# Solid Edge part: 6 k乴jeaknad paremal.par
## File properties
Author: Henri
Template: Normal.par
Last saved by: Henri
Revision: 20
Application: Solid Edge
Accuracy: 0,990
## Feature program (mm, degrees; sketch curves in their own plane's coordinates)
sketch used by "unnamed Protrusion 1" plane through (0.1912, -510.5703, 43.2891) normal (0, -0.948683, 0.316228) x-axis (1, 0, 0)
  line (-72.6912, 35.6338) -> (17.3088, 35.6338)
  line (22.3088, 30.6338) -> (22.3088, 15.6338)
  line (-187.6912, 30.6338) -> (-187.6912, 15.6338)
  line (-72.6912, 10.6338) -> (17.3088, 10.6338)
  line (-87.6912, 30.6338) -> (-87.6912, 15.6338)
  line (-77.6912, 30.6338) -> (-77.6912, 15.6338)
  line (-182.6912, 10.6338) -> (-92.6912, 10.6338)
  line (-182.6912, 35.6338) -> (-92.6912, 35.6338)
  arc centre (-182.6912, 30.6338) radius 5 from (-187.6912, 30.6338) to (-182.6912, 35.6338) cw
  arc centre (-182.6912, 15.6338) radius 5 from (-187.6912, 15.6338) to (-182.6912, 10.6338) ccw
  arc centre (-92.6912, 15.6338) radius 5 from (-92.6912, 10.6338) to (-87.6912, 15.6338) ccw
  arc centre (-92.6912, 30.6338) radius 5 from (-87.6912, 30.6338) to (-92.6912, 35.6338) ccw
  arc centre (-72.6912, 30.6338) radius 5 from (-77.6912, 30.6338) to (-72.6912, 35.6338) cw
  arc centre (-72.6912, 15.6338) radius 5 from (-77.6912, 15.6338) to (-72.6912, 10.6338) ccw
  arc centre (17.3088, 15.6338) radius 5 from (17.3088, 10.6338) to (22.3088, 15.6338) ccw
  arc centre (17.3088, 30.6338) radius 5 from (22.3088, 30.6338) to (17.3088, 35.6338) ccw
extrude "unnamed Protrusion 1" add finite 5 along -normal
sketch for "ExtrudedProtrusion_14" #1 plane through (-137.5, -503.2547, 65.2358) normal (0, -0.948683, 0.316228) x-axis (1, 0, 0)
sketch for "ExtrudedProtrusion_14" #2 plane through (-137.5, -503.2547, 65.2358) normal (0, -0.948683, 0.316228) x-axis (1, 0, 0)
sketch for "ExtrudedProtrusion_14" #3 plane through (-137.5, -503.2547, 65.2358) normal (0, -0.948683, 0.316228) x-axis (1, 0, 0)
  line (-45, 11) -> (45, 11)
  arc centre (45, 7.5) radius 3.5 from (48.5, 7.5) to (45, 11) ccw
  line (48.5, 7.5) -> (48.5, -7.5)
  arc centre (45, -7.5) radius 3.5 from (45, -11) to (48.5, -7.5) ccw
  line (-45, -11) -> (45, -11)
  arc centre (-45, -7.5) radius 3.5 from (-48.5, -7.5) to (-45, -11) ccw
  line (-48.5, 7.5) -> (-48.5, -7.5)
  arc centre (-45, 7.5) radius 3.5 from (-48.5, 7.5) to (-45, 11) cw
sketch for "ExtrudedProtrusion_14" #4 plane through (-137.5, -503.2547, 65.2358) normal (0, -0.948683, 0.316228) x-axis (1, 0, 0)
  line (65, 14) -> (155, 14)
  arc centre (155, 7.5) radius 6.5 from (161.5, 7.5) to (155, 14) ccw
  line (161.5, 7.5) -> (161.5, -7.5)
  arc centre (155, -7.5) radius 6.5 from (155, -14) to (161.5, -7.5) ccw
  line (65, -14) -> (155, -14)
  arc centre (65, -7.5) radius 6.5 from (58.5, -7.5) to (65, -14) ccw
  line (58.5, 7.5) -> (58.5, -7.5)
  arc centre (65, 7.5) radius 6.5 from (58.5, 7.5) to (65, 14) cw
extrude "ExtrudedProtrusion_14" add finite 1.5 along +normal
fillet "Round_19" radius 0.5
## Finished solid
Body 1: solid body, 88 faces, 208 edges, 128 vertices, 2 separate solids.
  Faces by surface: cylinder 40, plane 32, torus 16
  Edges by curve: line 112, circle 96
Bounding box of the edges (mm; curved faces can reach further): 213.000 x 14.414 x 27.063, from (-189, -508.9725, 51.7961) to (24, -494.5585, 78.8592).
Cylindrical faces by radius (mm): R0.5 x16, R3.5 x8, R5 x8, R6.5 x8
Toroidal faces (ring radius, tube radius in mm): R4 r0.5 x8, R6 r0.5 x8
Planar faces by outward normal: +x 6, -x 6, oblique 20
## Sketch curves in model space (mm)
line (-182.5, -498.8276, 78.5173) -> (-92.5, -498.8276, 78.5173)
arc centre (-92.5, -500.883, 72.3509) radius 6.5 from (-86, -500.883, 72.3509) through (-88.0394, -499.3879, 76.8362) to (-92.5, -498.8276, 78.5173)
line (-86, -500.883, 72.3509) -> (-86, -505.6265, 58.1206)
arc centre (-92.5, -505.6265, 58.1206) radius 6.5 from (-92.5, -507.6819, 51.9542) through (-87.7721, -507.037, 53.889) to (-86, -505.6265, 58.1206)
line (-182.5, -507.6819, 51.9542) -> (-92.5, -507.6819, 51.9542)
arc centre (-182.5, -505.6265, 58.1206) radius 6.5 from (-189, -505.6265, 58.1206) through (-186.9606, -507.1216, 53.6353) to (-182.5, -507.6819, 51.9542)
line (-189, -500.883, 72.3509) -> (-189, -505.6265, 58.1206)
arc centre (-182.5, -500.883, 72.3509) radius 6.5 from (-189, -500.883, 72.3509) through (-186.9606, -499.3879, 76.8362) to (-182.5, -498.8276, 78.5173)
line (-182.5, -499.7762, 75.6713) -> (-92.5, -499.7762, 75.6713)
arc centre (-92.5, -500.883, 72.3509) radius 3.5 from (-89, -500.883, 72.3509) through (-90.0982, -500.078, 74.7661) to (-92.5, -499.7762, 75.6713)
line (-89, -500.883, 72.3509) -> (-89, -505.6265, 58.1206)
arc centre (-92.5, -505.6265, 58.1206) radius 3.5 from (-92.5, -506.7333, 54.8002) through (-89.9542, -506.386, 55.842) to (-89, -505.6265, 58.1206)
line (-182.5, -506.7333, 54.8002) -> (-92.5, -506.7333, 54.8002)
arc centre (-182.5, -505.6265, 58.1206) radius 3.5 from (-186, -505.6265, 58.1206) through (-184.9018, -506.4315, 55.7055) to (-182.5, -506.7333, 54.8002)
line (-186, -500.883, 72.3509) -> (-186, -505.6265, 58.1206)
arc centre (-182.5, -500.883, 72.3509) radius 3.5 from (-186, -500.883, 72.3509) through (-184.9018, -500.078, 74.7661) to (-182.5, -499.7762, 75.6713)
arc centre (17.5, -500.883, 72.3509) radius 6.5 from (24, -500.883, 72.3509) through (21.9606, -499.3879, 76.8362) to (17.5, -498.8276, 78.5173)
line (24, -500.883, 72.3509) -> (24, -505.6265, 58.1206)
arc centre (17.5, -505.6265, 58.1206) radius 6.5 from (17.5, -507.6819, 51.9542) through (22.2279, -507.037, 53.889) to (24, -505.6265, 58.1206)
line (-72.5, -507.6819, 51.9542) -> (17.5, -507.6819, 51.9542)
arc centre (-72.5, -505.6265, 58.1206) radius 6.5 from (-79, -505.6265, 58.1206) through (-76.9606, -507.1216, 53.6353) to (-72.5, -507.6819, 51.9542)
line (-79, -500.883, 72.3509) -> (-79, -505.6265, 58.1206)
arc centre (-72.5, -500.883, 72.3509) radius 6.5 from (-79, -500.883, 72.3509) through (-76.9606, -499.3879, 76.8362) to (-72.5, -498.8276, 78.5173)
line (-72.5, -498.8276, 78.5173) -> (17.5, -498.8276, 78.5173)
line (-72.5, -499.7762, 75.6713) -> (17.5, -499.7762, 75.6713)
arc centre (17.5, -500.883, 72.3509) radius 3.5 from (21, -500.883, 72.3509) through (19.9018, -500.078, 74.7661) to (17.5, -499.7762, 75.6713)
line (21, -500.883, 72.3509) -> (21, -505.6265, 58.1206)
arc centre (17.5, -505.6265, 58.1206) radius 3.5 from (17.5, -506.7333, 54.8002) through (20.0458, -506.386, 55.842) to (21, -505.6265, 58.1206)
line (-72.5, -506.7333, 54.8002) -> (17.5, -506.7333, 54.8002)
arc centre (-72.5, -505.6265, 58.1206) radius 3.5 from (-76, -505.6265, 58.1206) through (-74.9018, -506.4315, 55.7055) to (-72.5, -506.7333, 54.8002)
line (-76, -500.883, 72.3509) -> (-76, -505.6265, 58.1206)
arc centre (-72.5, -500.883, 72.3509) radius 3.5 from (-76, -500.883, 72.3509) through (-74.9018, -500.078, 74.7661) to (-72.5, -499.7762, 75.6713)
arc centre (17.5, -500.883, 72.3509) radius 5 from (22.5, -500.883, 72.3509) through (20.9312, -499.733, 75.8011) to (17.5, -499.3019, 77.0943)
line (22.5, -500.883, 72.3509) -> (22.5, -505.6265, 58.1206)
arc centre (17.5, -505.6265, 58.1206) radius 5 from (17.5, -507.2076, 53.3772) through (21.1369, -506.7115, 54.8655) to (22.5, -505.6265, 58.1206)
line (-72.5, -507.2076, 53.3772) -> (17.5, -507.2076, 53.3772)
arc centre (-72.5, -505.6265, 58.1206) radius 5 from (-77.5, -505.6265, 58.1206) through (-75.9312, -506.7765, 54.6704) to (-72.5, -507.2076, 53.3772)
line (-77.5, -500.883, 72.3509) -> (-77.5, -505.6265, 58.1206)
arc centre (-72.5, -500.883, 72.3509) radius 5 from (-77.5, -500.883, 72.3509) through (-75.9312, -499.733, 75.8011) to (-72.5, -499.3019, 77.0943)
line (-72.5, -499.3019, 77.0943) -> (17.5, -499.3019, 77.0943)
arc centre (-182.5, -505.6265, 58.1206) radius 5 from (-187.5, -505.6265, 58.1206) through (-185.9312, -506.7765, 54.6704) to (-182.5, -507.2076, 53.3772)
line (-182.5, -507.2076, 53.3772) -> (-92.5, -507.2076, 53.3772)
arc centre (-92.5, -505.6265, 58.1206) radius 5 from (-92.5, -507.2076, 53.3772) through (-88.8631, -506.7115, 54.8655) to (-87.5, -505.6265, 58.1206)
line (-87.5, -500.883, 72.3509) -> (-87.5, -505.6265, 58.1206)
arc centre (-92.5, -500.883, 72.3509) radius 5 from (-87.5, -500.883, 72.3509) through (-89.0688, -499.733, 75.8011) to (-92.5, -499.3019, 77.0943)
line (-182.5, -499.3019, 77.0943) -> (-92.5, -499.3019, 77.0943)
arc centre (-182.5, -500.883, 72.3509) radius 5 from (-187.5, -500.883, 72.3509) through (-185.9312, -499.733, 75.8011) to (-182.5, -499.3019, 77.0943)
line (-187.5, -500.883, 72.3509) -> (-187.5, -505.6265, 58.1206)
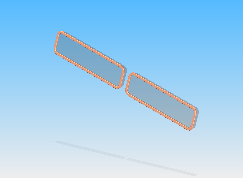
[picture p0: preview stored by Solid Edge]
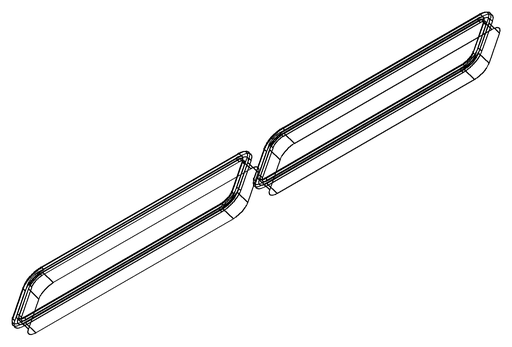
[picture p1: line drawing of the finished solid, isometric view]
